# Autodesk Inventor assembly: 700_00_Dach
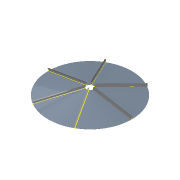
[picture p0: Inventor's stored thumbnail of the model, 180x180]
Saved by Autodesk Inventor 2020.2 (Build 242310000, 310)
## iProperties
_SolveAssemblyDoc: Frame Generator Solve Assembly
_Version: 15.0.0
Manager: www.cadconsulting.pl
Company: Fabian Stasiak CAD Consulting
Created: 2017-03
Part Number: 700_00_Dach
Document SubType Name: Assembly
Designer: F.Stasiak
Mass: 1.14319e+06 g
Surface Area: 465347 cm^2
Volume: 145630 cm^3
Density: 7.85 g/cm^3
Catalog Web Link: www.expertbooks.pl
Author: F.Stasiak
Subject: Zbiór ćwiczeń. Autodesk Inventor 2020. Kurs Professional
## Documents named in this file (3)
- C:\2020_Kurs_Professional\R4 MES\Dach\700_00_Dach.iam
- C:\2020_Kurs_Professional\R4 MES\Dach\700_01.ipt
- C:\2020_Kurs_Professional\R4 MES\Dach\700_00_Dach\Frame\Frame700_00_Dach.iam
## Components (2 placed, 2 different names)
1. 700_01:1
2. Frame700_00_Dach:1 [sub-assembly]
## Named parameters: sa_0 = 0, sa_2 = 0
